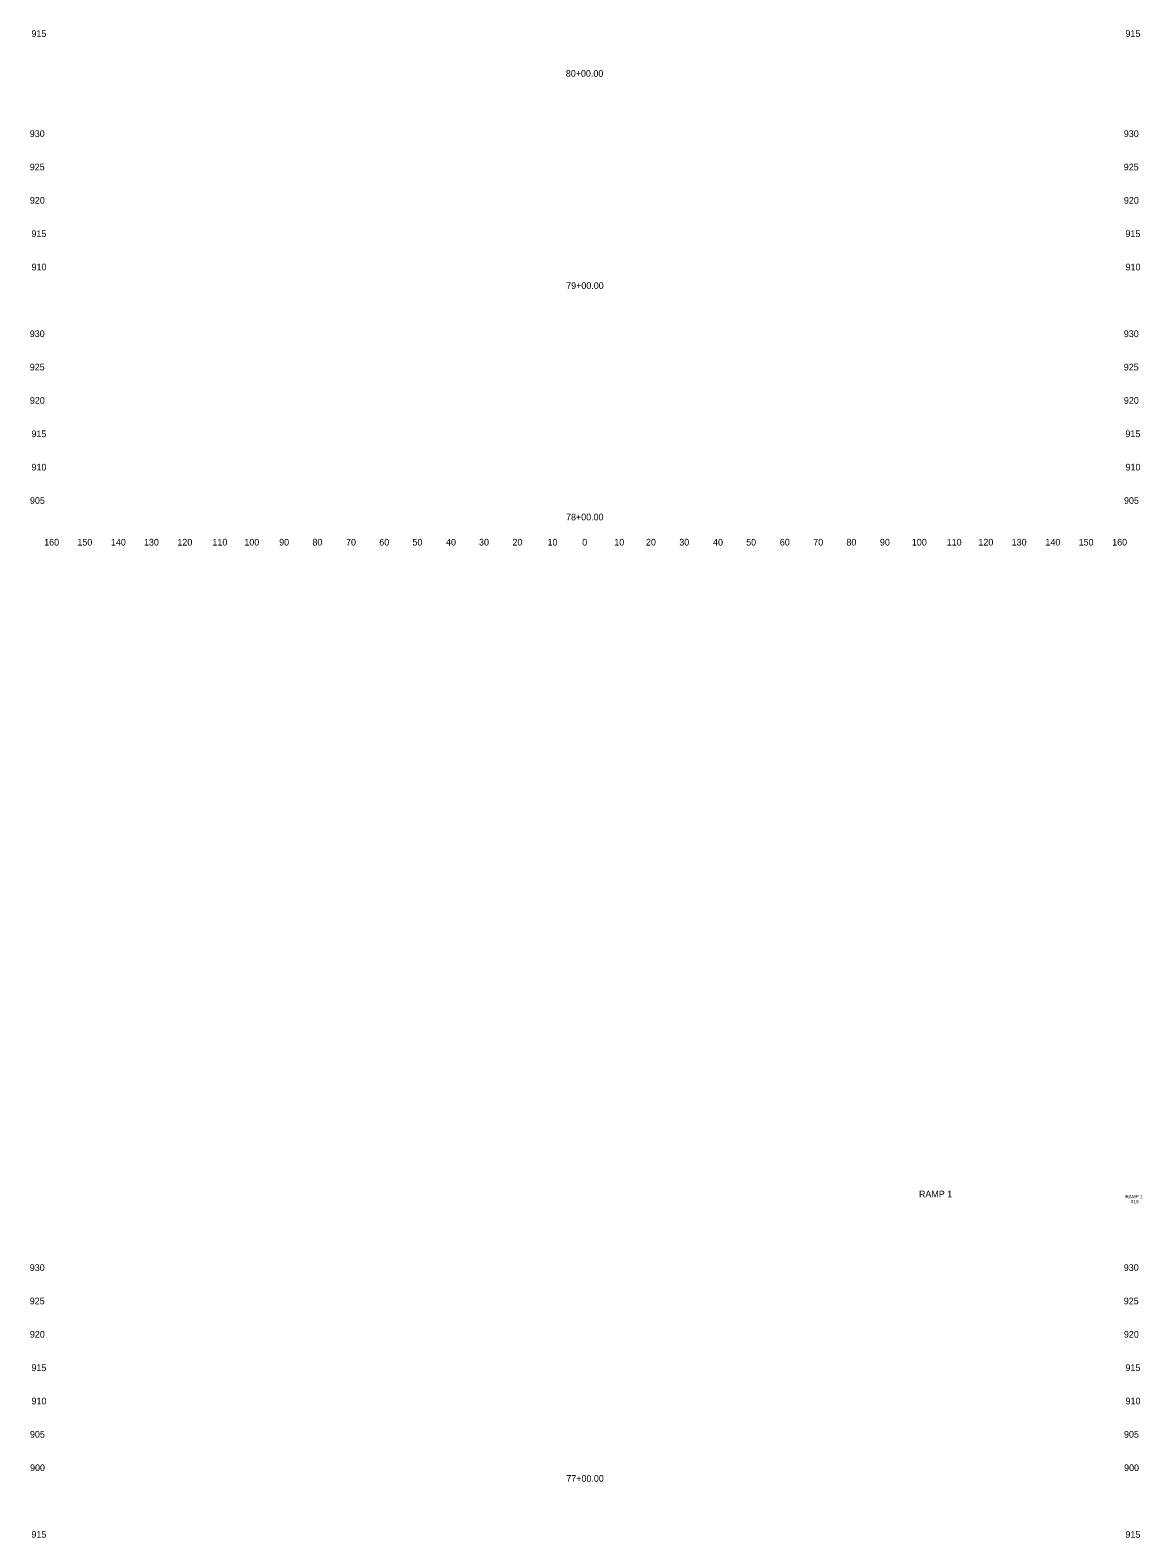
# Model space of a CAD drawing. Extents: x 4994 to 7869, y 4997 to 8804.
# Drawn here: x 5508.9 to 5842, y 7900 to 8352 of the extents above; entities that cross this region are included whole.
import ezdxf

# ---------------------------------------------------------------- set-up
doc = ezdxf.new("R2010")
doc.units = 0
for name, color, linetype in [('RD_SHT_ID', 7, 'Continuous'), ('RD_XS_TX_Offset', 7, 'Continuous'), ('RD_XS_TX_Station', 7, 'Continuous')]:
    doc.layers.add(name, color=color, linetype=linetype)

msp = doc.modelspace()

# ---------------------------------------------------------------- texts
at = {"layer": 'RD_SHT_ID'}
for s, height, p in [('RAMP 1', 2, (5775.19, 8002.06)), ('RAMP 1', 1, (5837.06, 8001.8)), ('X18', 1, (5838.57, 8000.3))]:
    msp.add_text(s, height=height, dxfattribs=at).set_placement(p)
at = {"layer": 'RD_XS_TX_Offset'}
for s, p in [('915', (5509.27, 8350)), ('915', (5837.07, 8350)), ('930', (5508.78, 8320)), ('930', (5836.58, 8320)), ('925', (5508.77, 8310)), ('925', (5836.57, 8310)), ('920', (5508.8, 8300)), ('920', (5836.6, 8300)), ('915', (5509.27, 8290)), ('915', (5837.07, 8290)), ('910', (5509.3, 8280)), ('910', (5837.1, 8280)), ('930', (5508.78, 8260)), ('930', (5836.58, 8260)), ('925', (5508.77, 8250)), ('925', (5836.57, 8250)), ('920', (5508.8, 8240)), ('920', (5836.6, 8240)), ('915', (5509.27, 8230)), ('915', (5837.07, 8230)), ('910', (5509.3, 8220)), ('910', (5837.1, 8220)), ('905', (5508.83, 8210)), ('905', (5836.63, 8210)), ('160', (5513.1, 8197.5)), ('150', (5523.04, 8197.5)), ('140', (5533.1, 8197.5)), ('130', (5542.99, 8197.5)), ('120', (5553.01, 8197.5)), ('110', (5563.51, 8197.5)), ('100', (5573.07, 8197.5)), ('90', (5583.5, 8197.5)), ('80', (5593.46, 8197.5)), ('70', (5603.54, 8197.5)), ('60', (5613.5, 8197.5)), ('50', (5623.43, 8197.5)), ('40', (5633.5, 8197.5)), ('30', (5643.39, 8197.5)), ('20', (5653.4, 8197.5)), ('10', (5663.91, 8197.5)), ('0', (5674.3, 8197.5)), ('0', (5674.3, 8197.5)), ('10', (5683.91, 8197.5)), ('20', (5693.4, 8197.5)), ('30', (5703.39, 8197.5)), ('40', (5713.5, 8197.5)), ('50', (5723.43, 8197.5)), ('60', (5733.5, 8197.5)), ('70', (5743.54, 8197.5)), ('80', (5753.46, 8197.5)), ('90', (5763.5, 8197.5)), ('100', (5773.07, 8197.5)), ('110', (5783.51, 8197.5)), ('120', (5793.01, 8197.5)), ('130', (5802.99, 8197.5)), ('140', (5813.1, 8197.5)), ('150', (5823.04, 8197.5)), ('160', (5833.1, 8197.5)), ('930', (5508.78, 7980)), ('930', (5836.58, 7980)), ('925', (5508.77, 7970)), ('925', (5836.57, 7970)), ('920', (5508.8, 7960)), ('920', (5836.6, 7960)), ('915', (5509.27, 7950)), ('915', (5837.07, 7950)), ('910', (5509.3, 7940)), ('910', (5837.1, 7940)), ('905', (5508.83, 7930)), ('905', (5836.63, 7930)), ('900', (5508.86, 7920)), ('900', (5836.66, 7920)), ('915', (5509.27, 7900)), ('915', (5837.07, 7900))]:
    msp.add_text(s, height=2, dxfattribs=at).set_placement(p)
at = {"layer": 'RD_XS_TX_Station'}
for s, p in [('80+00.00', (5669.39, 8338.06)), ('79+00.00', (5669.5, 8274.43)), ('78+00.00', (5669.46, 8205.04)), ('77+00.00', (5669.54, 7916.78))]:
    msp.add_text(s, height=2, dxfattribs=at).set_placement(p)

doc.saveas('drawing.dxf')
